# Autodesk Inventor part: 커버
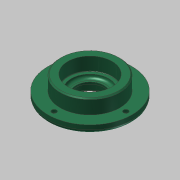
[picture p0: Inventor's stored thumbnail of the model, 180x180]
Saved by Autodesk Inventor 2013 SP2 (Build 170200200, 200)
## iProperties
Company: 한국ATC센터
Created: 2016-04
Part Number: 커버
Document SubType Name: Modeling
Designer: mdu
Density: 7.86 g/cm^3
Mass: 351.567 g
Surface Area: 161.165 cm^2
Volume: 44.7286 cm^3
Material: 강철, 연강
Author: mdu
Revision Number: 1
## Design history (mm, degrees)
sketch "스케치1"
  geometry: C1 r 38 at (0, 0); 1 further point
  constraints: 1 centre point, 1 coincident
  dimensions: "d0" = 76 diameter of C1
extrude "돌출1" new body sketch "스케치1" distance "d1" = 7; taper "d2" = 0 deg
sketch "스케치2"
  geometry: C1 r 27 at (0, 0); 1 further point
  constraints: 1 centre point, 1 coincident
  dimensions: "d3" = 54 diameter of C1
extrude "돌출2" join sketch "스케치2" distance "d4" = 13; taper "d5" = 0 deg
sketch "스케치3"
  geometry: C1 r 20 at (0, 0); 1 further point
  constraints: 1 centre point, 1 coincident
  dimensions: "d6" = 40 diameter of C1
extrude "돌출3" join sketch "스케치3" distance "d7" = 5; taper "d8" = 0 deg
hole "구멍1" diameter "d11" = 25; stored, may be unused: countersink angle "d15" = 90 deg, drill point angle "d17" = 118 deg; dims "d9" = 10, "d10" = 10, "d12" = 6, "d13" = 32, "d14" = 8.3, "d16" = 8
hole "구멍2" diameter "d20" = 34; stored, may be unused: countersink angle "d24" = 90 deg, drill point angle "d26" = 0 deg; dims "d18" = 10, "d19" = 10, "d21" = 6, "d22" = 40, "d23" = 12, "d25" = 3
fillet "모깎기2" dims "d34" = 3
fillet "모깎기1" dims "d27" = 0.3
chamfer "모따기1" distance "d28" = 1; stored, may be unused: second distance "d29" = 2, angle "d30" = 45 deg
chamfer "모따기2" distance "d31" = 1.2; stored, may be unused: second distance "d32" = 2, angle "d33" = 30 deg
sketch "스케치4" dims "d35" = 65
  geometry: 3 further points
  constraints: 2 horizontal alignment, 1 coincident, 2 other
hole "구멍3" sketch "스케치4" at (32.5, 0) diameter "d36" = 4.5; stored, may be unused: countersink angle "d40" = 90 deg, drill point angle "d42" = 118 deg; dims "d37" = 6, "d38" = 8, "d39" = 4.4, "d41" = 13
node "솔리드1"
pattern_circular "원형 패턴1" dims angle "d44" = 360 deg
